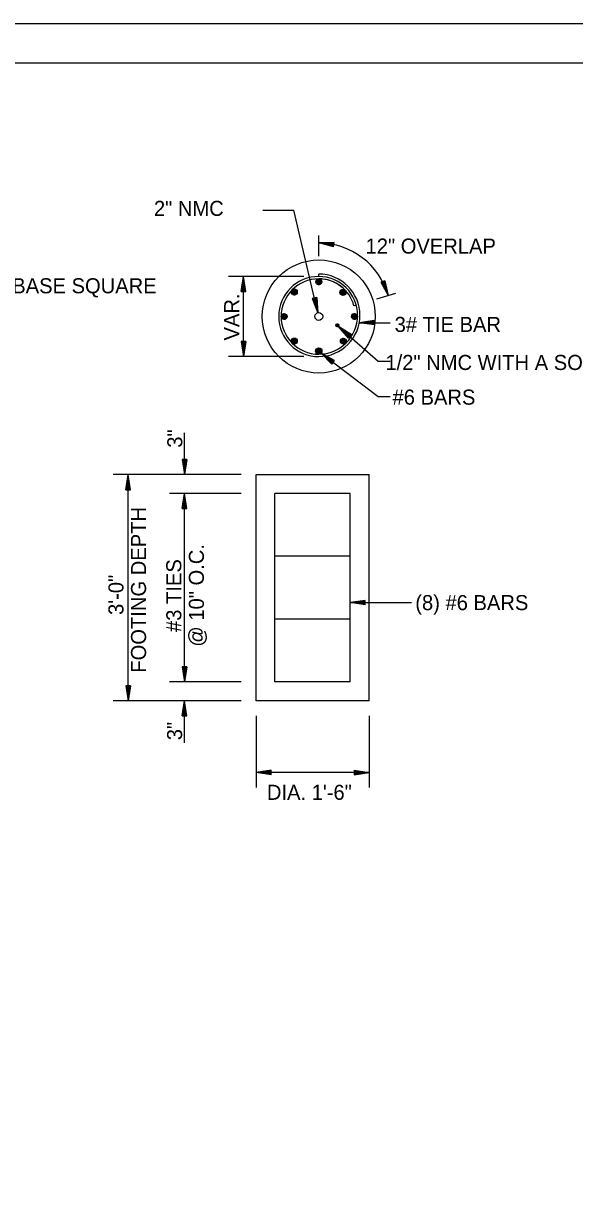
# Model space of a CAD drawing. Extents: x 1370050 to 1370716, y 380076 to 380502.
# Drawn here: x 1370415.9 to 1370525.6, y 380266.8 to 380502.4 of the extents above; entities that cross this region are included whole.
import ezdxf

# ---------------------------------------------------------------- set-up
doc = ezdxf.new("R2010")
doc.units = 0
for name, color, linetype in [('R_Border', 7, 'Continuous'), ('R_Grid', 7, 'Continuous'), ('R_No Plot', 7, 'Continuous')]:
    doc.layers.add(name, color=color, linetype=linetype)

msp = doc.modelspace()

# ---------------------------------------------------------------- linework, layer by layer
at = {"layer": 'R_Border'}
msp.add_line((1370074.49, 380494.58), (1370706.85, 380494.58), dxfattribs=at)
at = {"layer": 'R_Grid'}
for p, q in [((1370463.57, 380465.27), (1370469.71, 380465.27)), ((1370474.52, 380444.85), (1370469.71, 380465.27)), ((1370474.7, 380456.09), (1370474.7, 380460.2)), ((1370477.74, 380458.83), (1370474.71, 380458.76)), ((1370477.62, 380457.93), (1370474.71, 380458.76)), ((1370477.73, 380458.75), (1370475.2, 380458.7)), ((1370477.63, 380458.01), (1370475.2, 380458.7)), ((1370477.72, 380458.68), (1370475.71, 380458.63)), ((1370477.64, 380458.08), (1370475.71, 380458.63)), ((1370477.71, 380458.6), (1370476.21, 380458.57)), ((1370477.65, 380458.16), (1370476.21, 380458.57)), ((1370477.7, 380458.53), (1370476.71, 380458.5)), ((1370477.66, 380458.24), (1370476.71, 380458.5)), ((1370477.62, 380457.93), (1370477.74, 380458.83)), ((1370477.69, 380458.45), (1370477.21, 380458.44)), ((1370477.67, 380458.31), (1370477.21, 380458.44)), ((1370471.7, 380452.06), (1370456.7, 380452.06)), ((1370459.25, 380449.06), (1370459.7, 380452.06)), ((1370459.33, 380449.06), (1370459.7, 380451.56)), ((1370459.7, 380436.12), (1370459.7, 380452.06)), ((1370460.15, 380449.06), (1370459.7, 380452.06)), ((1370460.08, 380449.06), (1370459.7, 380451.56)), ((1370474.1, 380450.96), (1370474.73, 380451.59)), ((1370474.11, 380450.87), (1370474.82, 380451.58)), ((1370474.11, 380451.07), (1370474.62, 380451.58)), ((1370474.14, 380450.79), (1370474.91, 380451.55)), ((1370474.15, 380451.22), (1370474.47, 380451.54)), ((1370474.17, 380450.71), (1370474.98, 380451.52)), ((1370474.21, 380450.65), (1370475.05, 380451.48)), ((1370474.26, 380450.59), (1370475.1, 380451.43)), ((1370474.7, 380452.06), (1370474.7, 380452.53)), ((1370459.25, 380449.06), (1370460.15, 380449.06)), ((1370459.4, 380449.06), (1370459.7, 380451.04)), ((1370459.48, 380449.06), (1370459.7, 380450.54)), ((1370459.56, 380449.06), (1370459.7, 380450.03)), ((1370459.63, 380449.06), (1370459.7, 380449.53)), ((1370460, 380449.06), (1370459.7, 380451.04)), ((1370459.92, 380449.06), (1370459.7, 380450.54)), ((1370459.85, 380449.06), (1370459.7, 380450.03)), ((1370459.77, 380449.06), (1370459.7, 380449.53)), ((1370469.22, 380448.99), (1370469.8, 380449.57)), ((1370469.23, 380448.89), (1370469.9, 380449.56)), ((1370469.24, 380449.12), (1370469.67, 380449.55)), ((1370469.25, 380448.81), (1370469.99, 380449.55)), ((1370469.27, 380448.73), (1370470.06, 380449.52)), ((1370469.31, 380448.66), (1370470.13, 380449.48)), ((1370469.34, 380449.32), (1370469.47, 380449.46)), ((1370469.35, 380448.59), (1370470.2, 380449.44)), ((1370469.4, 380448.54), (1370470.25, 380449.39)), ((1370469.46, 380448.49), (1370470.3, 380449.33)), ((1370469.52, 380448.45), (1370470.34, 380449.27)), ((1370469.6, 380448.41), (1370470.38, 380449.2)), ((1370469.68, 380448.39), (1370470.4, 380449.12)), ((1370474.31, 380450.53), (1370475.16, 380451.38)), ((1370474.37, 380450.49), (1370475.2, 380451.32)), ((1370474.44, 380450.45), (1370475.24, 380451.25)), ((1370474.51, 380450.42), (1370475.27, 380451.18)), ((1370474.6, 380450.4), (1370475.29, 380451.09)), ((1370474.7, 380450.39), (1370475.3, 380451)), ((1370474.81, 380450.4), (1370475.29, 380450.88)), ((1370474.97, 380450.45), (1370475.24, 380450.72)), ((1370478.91, 380448.95), (1370479.46, 380449.5)), ((1370478.92, 380448.85), (1370479.57, 380449.5)), ((1370478.93, 380448.76), (1370479.66, 380449.48)), ((1370478.94, 380449.09), (1370479.33, 380449.47)), ((1370478.96, 380448.68), (1370479.74, 380449.46)), ((1370478.99, 380448.6), (1370479.81, 380449.42)), ((1370479.03, 380448.54), (1370479.87, 380449.38)), ((1370479.08, 380448.48), (1370479.93, 380449.33)), ((1370479.14, 380448.43), (1370479.98, 380449.28)), ((1370479.2, 380448.39), (1370480.02, 380449.21)), ((1370479.27, 380448.35), (1370480.06, 380449.14)), ((1370479.35, 380448.32), (1370480.09, 380449.07)), ((1370487.87, 380451.22), (1370487.03, 380450.9)), ((1370487.03, 380450.9), (1370488.52, 380448.26)), ((1370487.1, 380450.93), (1370488.34, 380448.73)), ((1370487.17, 380450.96), (1370488.16, 380449.21)), ((1370487.24, 380450.98), (1370487.98, 380449.68)), ((1370487.31, 380451.01), (1370487.8, 380450.15)), ((1370487.38, 380451.04), (1370487.62, 380450.62)), ((1370487.52, 380451.09), (1370487.62, 380450.62)), ((1370487.59, 380451.11), (1370487.8, 380450.15)), ((1370487.66, 380451.14), (1370487.98, 380449.68)), ((1370487.73, 380451.17), (1370488.16, 380449.21)), ((1370487.8, 380451.2), (1370488.34, 380448.73)), ((1370487.87, 380451.22), (1370488.52, 380448.26)), ((1370469.77, 380448.37), (1370470.42, 380449.03)), ((1370469.87, 380448.37), (1370470.42, 380448.92)), ((1370470, 380448.4), (1370470.39, 380448.79)), ((1370474.29, 380447.88), (1370473.41, 380447.67)), ((1370473.41, 380447.67), (1370474.52, 380444.85)), ((1370473.49, 380447.69), (1370474.41, 380445.34)), ((1370473.56, 380447.71), (1370474.3, 380445.84)), ((1370473.63, 380447.72), (1370474.18, 380446.33)), ((1370473.71, 380447.74), (1370474.07, 380446.82)), ((1370473.78, 380447.76), (1370473.96, 380447.31)), ((1370473.92, 380447.79), (1370473.96, 380447.31)), ((1370473.99, 380447.81), (1370474.07, 380446.82)), ((1370474.07, 380447.82), (1370474.18, 380446.33)), ((1370474.14, 380447.84), (1370474.3, 380445.84)), ((1370474.22, 380447.86), (1370474.41, 380445.34)), ((1370474.29, 380447.88), (1370474.52, 380444.85)), ((1370479.44, 380448.31), (1370480.11, 380448.98)), ((1370479.54, 380448.3), (1370480.11, 380448.88)), ((1370479.66, 380448.32), (1370480.09, 380448.75)), ((1370479.86, 380448.41), (1370480, 380448.56)), ((1370489.96, 380448.69), (1370486.19, 380447.56)), ((1370467.2, 380444.12), (1370467.77, 380444.69)), ((1370467.21, 380444.02), (1370467.87, 380444.69)), ((1370467.22, 380443.93), (1370467.96, 380444.67)), ((1370467.22, 380444.25), (1370467.65, 380444.67)), ((1370467.25, 380443.85), (1370468.04, 380444.64)), ((1370467.29, 380443.78), (1370468.11, 380444.6)), ((1370467.32, 380444.45), (1370467.44, 380444.57)), ((1370467.33, 380443.72), (1370468.17, 380444.56)), ((1370467.38, 380443.66), (1370468.23, 380444.51)), ((1370467.44, 380443.61), (1370468.28, 380444.45)), ((1370467.5, 380443.57), (1370468.32, 380444.39)), ((1370467.57, 380443.54), (1370468.36, 380444.32)), ((1370481.21, 380444.1), (1370481.8, 380444.69)), ((1370481.21, 380444), (1370481.9, 380444.68)), ((1370481.22, 380444.22), (1370481.68, 380444.68)), ((1370481.23, 380443.91), (1370481.99, 380444.66)), ((1370481.26, 380443.84), (1370482.06, 380444.63)), ((1370481.29, 380444.39), (1370481.51, 380444.61)), ((1370481.3, 380443.77), (1370482.13, 380444.6)), ((1370481.35, 380443.71), (1370482.19, 380444.55)), ((1370481.4, 380443.65), (1370482.25, 380444.5)), ((1370481.46, 380443.6), (1370482.29, 380444.44)), ((1370481.52, 380443.56), (1370482.34, 380444.38)), ((1370482.17, 380446.34), (1370481.72, 380446.21)), ((1370467.65, 380443.51), (1370468.38, 380444.24)), ((1370467.74, 380443.49), (1370468.4, 380444.15)), ((1370467.85, 380443.49), (1370468.4, 380444.04)), ((1370467.98, 380443.52), (1370468.37, 380443.91)), ((1370478.09, 380442.34), (1370478.4, 380442.65)), ((1370478.1, 380442.25), (1370478.49, 380442.64)), ((1370478.12, 380442.48), (1370478.25, 380442.62)), ((1370478.13, 380442.18), (1370478.56, 380442.61)), ((1370478.18, 380442.12), (1370478.62, 380442.56)), ((1370478.24, 380442.07), (1370478.67, 380442.5)), ((1370478.31, 380442.04), (1370478.7, 380442.43)), ((1370478.41, 380442.03), (1370478.71, 380442.33)), ((1370478.56, 380442.07), (1370478.67, 380442.18)), ((1370478.62, 380442.11), (1370486.51, 380435.23)), ((1370480.6, 380439.81), (1370478.62, 380442.11)), ((1370481.18, 380440.49), (1370478.62, 380442.11)), ((1370481.59, 380443.53), (1370482.37, 380444.3)), ((1370481.68, 380443.5), (1370482.39, 380444.22)), ((1370481.77, 380443.49), (1370482.41, 380444.13)), ((1370481.88, 380443.49), (1370482.4, 380444.02)), ((1370482.02, 380443.53), (1370482.37, 380443.88)), ((1370485.77, 380443.31), (1370482.77, 380442.86)), ((1370482.77, 380442.86), (1370488.91, 380442.86)), ((1370485.77, 380442.41), (1370482.77, 380442.86)), ((1370485.77, 380443.23), (1370483.27, 380442.86)), ((1370485.77, 380442.48), (1370483.27, 380442.86)), ((1370485.77, 380443.15), (1370483.79, 380442.86)), ((1370485.77, 380442.56), (1370483.79, 380442.86)), ((1370485.77, 380443.08), (1370484.29, 380442.86)), ((1370485.77, 380442.63), (1370484.29, 380442.86)), ((1370485.77, 380443), (1370484.8, 380442.86)), ((1370485.77, 380442.71), (1370484.8, 380442.86)), ((1370485.77, 380442.93), (1370485.3, 380442.86)), ((1370485.77, 380442.79), (1370485.3, 380442.86)), ((1370485.77, 380442.41), (1370485.77, 380443.31)), ((1370469.22, 380439.16), (1370469.88, 380439.81)), ((1370469.22, 380439.26), (1370469.77, 380439.81)), ((1370469.24, 380439.06), (1370469.97, 380439.79)), ((1370469.25, 380439.39), (1370469.64, 380439.78)), ((1370469.27, 380438.98), (1370470.05, 380439.77)), ((1370469.3, 380438.91), (1370470.12, 380439.73)), ((1370469.34, 380438.85), (1370470.18, 380439.69)), ((1370469.39, 380438.79), (1370470.24, 380439.64)), ((1370480.64, 380439.87), (1370479, 380441.79)), ((1370481.14, 380440.44), (1370479, 380441.79)), ((1370479.01, 380439.11), (1370479.68, 380439.78)), ((1370479.01, 380439.21), (1370479.58, 380439.78)), ((1370479.03, 380439.02), (1370479.77, 380439.76)), ((1370479.03, 380439.34), (1370479.46, 380439.76)), ((1370479.06, 380438.94), (1370479.85, 380439.73)), ((1370479.1, 380438.87), (1370479.92, 380439.7)), ((1370479.13, 380439.54), (1370479.25, 380439.66)), ((1370479.14, 380438.81), (1370479.98, 380439.65)), ((1370481.09, 380440.38), (1370479.39, 380441.45)), ((1370480.69, 380439.93), (1370479.39, 380441.45)), ((1370480.74, 380439.98), (1370479.77, 380441.12)), ((1370481.04, 380440.32), (1370479.77, 380441.12)), ((1370480.99, 380440.26), (1370480.15, 380440.79)), ((1370480.79, 380440.04), (1370480.15, 380440.79)), ((1370480.94, 380440.21), (1370480.53, 380440.46)), ((1370480.84, 380440.1), (1370480.53, 380440.46)), ((1370480.6, 380439.81), (1370481.18, 380440.49)), ((1370459.25, 380439.12), (1370459.7, 380436.12)), ((1370460.15, 380439.12), (1370459.25, 380439.12)), ((1370459.33, 380439.12), (1370459.7, 380436.62)), ((1370459.4, 380439.12), (1370459.7, 380437.14)), ((1370459.48, 380439.12), (1370459.7, 380437.64)), ((1370459.55, 380439.12), (1370459.7, 380438.15)), ((1370459.63, 380439.12), (1370459.7, 380438.65)), ((1370460.15, 380439.12), (1370459.7, 380436.12)), ((1370459.85, 380439.12), (1370459.7, 380438.15)), ((1370460, 380439.12), (1370459.7, 380437.14)), ((1370460.08, 380439.12), (1370459.7, 380436.62)), ((1370459.92, 380439.12), (1370459.7, 380437.64)), ((1370459.77, 380439.12), (1370459.7, 380438.65)), ((1370469.45, 380438.74), (1370470.29, 380439.59)), ((1370469.51, 380438.7), (1370470.33, 380439.52)), ((1370469.58, 380438.66), (1370470.37, 380439.45)), ((1370469.66, 380438.63), (1370470.4, 380439.38)), ((1370469.75, 380438.62), (1370470.42, 380439.29)), ((1370469.85, 380438.61), (1370470.42, 380439.19)), ((1370469.97, 380438.63), (1370470.4, 380439.06)), ((1370470.17, 380438.72), (1370470.31, 380438.86)), ((1370474.08, 380437.16), (1370474.76, 380437.84)), ((1370474.08, 380437.26), (1370474.65, 380437.84)), ((1370474.09, 380437.07), (1370474.85, 380437.82)), ((1370474.1, 380437.39), (1370474.52, 380437.81)), ((1370474.12, 380436.99), (1370474.93, 380437.8)), ((1370474.15, 380436.91), (1370475, 380437.76)), ((1370474.19, 380436.85), (1370475.07, 380437.72)), ((1370474.24, 380437.64), (1370474.28, 380437.68)), ((1370474.24, 380436.79), (1370475.13, 380437.67)), ((1370474.3, 380436.74), (1370475.18, 380437.62)), ((1370474.36, 380436.69), (1370475.22, 380437.56)), ((1370474.42, 380436.65), (1370475.26, 380437.49)), ((1370474.5, 380436.62), (1370475.29, 380437.42)), ((1370474.58, 380436.6), (1370475.32, 380437.33)), ((1370479.19, 380438.75), (1370480.04, 380439.6)), ((1370479.25, 380438.7), (1370480.09, 380439.54)), ((1370479.31, 380438.66), (1370480.13, 380439.48)), ((1370479.38, 380438.63), (1370480.16, 380439.41)), ((1370479.46, 380438.6), (1370480.19, 380439.33)), ((1370479.55, 380438.58), (1370480.21, 380439.24)), ((1370479.66, 380438.58), (1370480.21, 380439.13)), ((1370479.79, 380438.61), (1370480.18, 380439)), ((1370471.7, 380436.12), (1370456.7, 380436.12)), ((1370474.68, 380436.59), (1370475.33, 380437.24)), ((1370474.79, 380436.6), (1370475.32, 380437.13)), ((1370474.94, 380436.64), (1370475.28, 380436.98)), ((1370475.15, 380436.78), (1370486.51, 380428.19)), ((1370477.28, 380434.61), (1370475.15, 380436.78)), ((1370477.82, 380435.33), (1370475.15, 380436.78)), ((1370477.32, 380434.67), (1370475.55, 380436.48)), ((1370477.77, 380435.27), (1370475.55, 380436.48)), ((1370477.73, 380435.21), (1370475.96, 380436.17)), ((1370477.37, 380434.73), (1370475.96, 380436.17)), ((1370477.41, 380434.79), (1370476.36, 380435.86)), ((1370477.68, 380435.15), (1370476.36, 380435.86)), ((1370477.63, 380435.09), (1370476.77, 380435.56)), ((1370477.46, 380434.86), (1370476.77, 380435.56)), ((1370477.59, 380435.03), (1370477.17, 380435.26)), ((1370477.5, 380434.92), (1370477.17, 380435.26)), ((1370477.28, 380434.61), (1370477.82, 380435.33)), ((1370486.51, 380435.23), (1370488.91, 380435.23)), ((1370486.51, 380428.19), (1370488.91, 380428.19)), ((1370447.97, 380412.62), (1370447.97, 380420.96)), ((1370447.52, 380415.62), (1370447.97, 380412.62)), ((1370448.42, 380415.62), (1370447.52, 380415.62)), ((1370447.59, 380415.62), (1370447.97, 380413.12)), ((1370447.67, 380415.62), (1370447.97, 380413.64)), ((1370447.74, 380415.62), (1370447.97, 380414.14)), ((1370447.82, 380415.62), (1370447.97, 380414.65)), ((1370447.9, 380415.62), (1370447.97, 380415.15)), ((1370448.42, 380415.62), (1370447.97, 380412.62)), ((1370448.11, 380415.62), (1370447.97, 380414.65)), ((1370448.27, 380415.62), (1370447.97, 380413.64)), ((1370448.34, 380415.62), (1370447.97, 380413.12)), ((1370448.19, 380415.62), (1370447.97, 380414.14)), ((1370448.04, 380415.62), (1370447.97, 380415.15)), ((1370459.22, 380412.62), (1370433.72, 380412.62)), ((1370436.27, 380409.62), (1370436.72, 380412.62)), ((1370436.34, 380409.62), (1370436.72, 380412.12)), ((1370436.42, 380409.62), (1370436.72, 380411.61)), ((1370436.72, 380367.62), (1370436.72, 380412.62)), ((1370437.17, 380409.62), (1370436.72, 380412.62)), ((1370437.09, 380409.62), (1370436.72, 380412.12)), ((1370437.02, 380409.62), (1370436.72, 380411.61)), ((1370462.22, 380367.62), (1370462.22, 380412.62)), ((1370462.22, 380412.62), (1370484.72, 380412.62)), ((1370484.72, 380367.62), (1370484.72, 380412.62)), ((1370436.27, 380409.62), (1370437.17, 380409.62)), ((1370436.49, 380409.62), (1370436.72, 380411.11)), ((1370436.57, 380409.62), (1370436.72, 380410.6)), ((1370436.65, 380409.62), (1370436.72, 380410.1)), ((1370436.94, 380409.62), (1370436.72, 380411.11)), ((1370436.86, 380409.62), (1370436.72, 380410.6)), ((1370436.79, 380409.62), (1370436.72, 380410.1)), ((1370459.22, 380408.87), (1370444.97, 380408.87)), ((1370447.52, 380405.87), (1370447.97, 380408.87)), ((1370447.59, 380405.87), (1370447.97, 380408.37)), ((1370447.67, 380405.87), (1370447.97, 380407.86)), ((1370447.74, 380405.87), (1370447.97, 380407.36)), ((1370447.82, 380405.87), (1370447.97, 380406.85)), ((1370447.97, 380371.37), (1370447.97, 380408.87)), ((1370448.42, 380405.87), (1370447.97, 380408.87)), ((1370448.34, 380405.87), (1370447.97, 380408.37)), ((1370448.27, 380405.87), (1370447.97, 380407.86)), ((1370448.19, 380405.87), (1370447.97, 380407.36)), ((1370448.11, 380405.87), (1370447.97, 380406.85)), ((1370480.97, 380408.87), (1370465.97, 380408.87)), ((1370465.97, 380371.37), (1370465.97, 380408.87)), ((1370480.97, 380371.37), (1370480.97, 380408.87)), ((1370447.52, 380405.87), (1370448.42, 380405.87)), ((1370447.9, 380405.87), (1370447.97, 380406.35)), ((1370448.04, 380405.87), (1370447.97, 380406.35)), ((1370480.97, 380396.37), (1370465.97, 380396.37)), ((1370483.97, 380387.61), (1370480.97, 380387.16)), ((1370483.97, 380386.71), (1370480.97, 380387.16)), ((1370480.97, 380387.16), (1370493.19, 380387.16)), ((1370483.97, 380387.54), (1370481.47, 380387.16)), ((1370483.97, 380386.79), (1370481.47, 380387.16)), ((1370483.97, 380387.46), (1370481.99, 380387.16)), ((1370483.97, 380386.86), (1370481.99, 380387.16)), ((1370483.97, 380387.39), (1370482.49, 380387.16)), ((1370483.97, 380386.94), (1370482.49, 380387.16)), ((1370483.97, 380387.31), (1370483, 380387.16)), ((1370483.97, 380387.02), (1370483, 380387.16)), ((1370483.97, 380387.23), (1370483.5, 380387.16)), ((1370483.97, 380387.09), (1370483.5, 380387.16)), ((1370483.97, 380386.71), (1370483.97, 380387.61)), ((1370480.97, 380383.87), (1370465.97, 380383.87)), ((1370447.52, 380374.37), (1370447.97, 380371.37)), ((1370448.42, 380374.37), (1370447.52, 380374.37)), ((1370447.59, 380374.37), (1370447.97, 380371.87)), ((1370447.67, 380374.37), (1370447.97, 380372.39)), ((1370447.74, 380374.37), (1370447.97, 380372.89)), ((1370447.82, 380374.37), (1370447.97, 380373.4)), ((1370447.9, 380374.37), (1370447.97, 380373.9)), ((1370448.42, 380374.37), (1370447.97, 380371.37)), ((1370448.11, 380374.37), (1370447.97, 380373.4)), ((1370448.27, 380374.37), (1370447.97, 380372.39)), ((1370448.34, 380374.37), (1370447.97, 380371.87)), ((1370448.19, 380374.37), (1370447.97, 380372.89)), ((1370448.04, 380374.37), (1370447.97, 380373.9)), ((1370459.22, 380371.37), (1370444.97, 380371.37)), ((1370480.97, 380371.37), (1370465.97, 380371.37)), ((1370436.27, 380370.62), (1370436.72, 380367.62)), ((1370437.17, 380370.62), (1370436.27, 380370.62)), ((1370436.34, 380370.62), (1370436.72, 380368.12)), ((1370436.42, 380370.62), (1370436.72, 380368.64)), ((1370436.49, 380370.62), (1370436.72, 380369.14)), ((1370436.57, 380370.62), (1370436.72, 380369.65)), ((1370436.65, 380370.62), (1370436.72, 380370.15)), ((1370437.17, 380370.62), (1370436.72, 380367.62)), ((1370436.86, 380370.62), (1370436.72, 380369.65)), ((1370437.02, 380370.62), (1370436.72, 380368.64)), ((1370437.09, 380370.62), (1370436.72, 380368.12)), ((1370436.94, 380370.62), (1370436.72, 380369.14)), ((1370436.79, 380370.62), (1370436.72, 380370.15)), ((1370459.22, 380367.62), (1370433.72, 380367.62)), ((1370447.52, 380364.62), (1370447.97, 380367.62)), ((1370447.59, 380364.62), (1370447.97, 380367.12)), ((1370447.67, 380364.62), (1370447.97, 380366.61)), ((1370447.97, 380359.28), (1370447.97, 380367.62)), ((1370448.42, 380364.62), (1370447.97, 380367.62)), ((1370448.34, 380364.62), (1370447.97, 380367.12)), ((1370448.27, 380364.62), (1370447.97, 380366.61)), ((1370484.72, 380367.62), (1370462.22, 380367.62)), ((1370447.52, 380364.62), (1370448.42, 380364.62)), ((1370447.74, 380364.62), (1370447.97, 380366.11)), ((1370447.82, 380364.62), (1370447.97, 380365.6)), ((1370447.9, 380364.62), (1370447.97, 380365.1)), ((1370448.19, 380364.62), (1370447.97, 380366.11)), ((1370448.11, 380364.62), (1370447.97, 380365.6)), ((1370448.04, 380364.62), (1370447.97, 380365.1)), ((1370462.22, 380364.62), (1370462.22, 380350.37)), ((1370484.72, 380364.62), (1370484.72, 380350.37)), ((1370465.22, 380353.82), (1370462.22, 380353.37)), ((1370484.72, 380353.37), (1370462.22, 380353.37)), ((1370465.22, 380352.92), (1370462.22, 380353.37)), ((1370465.22, 380353.75), (1370462.72, 380353.37)), ((1370465.22, 380353), (1370462.72, 380353.37)), ((1370465.22, 380353.67), (1370463.23, 380353.37)), ((1370465.22, 380353.07), (1370463.23, 380353.37)), ((1370465.22, 380353.6), (1370463.73, 380353.37)), ((1370465.22, 380353.15), (1370463.73, 380353.37)), ((1370465.22, 380353.52), (1370464.24, 380353.37)), ((1370465.22, 380353.23), (1370464.24, 380353.37)), ((1370465.22, 380353.44), (1370464.74, 380353.37)), ((1370465.22, 380353.3), (1370464.74, 380353.37)), ((1370465.22, 380352.92), (1370465.22, 380353.82)), ((1370481.72, 380353.82), (1370484.72, 380353.37)), ((1370481.72, 380353.82), (1370481.72, 380352.92)), ((1370481.72, 380353.75), (1370484.22, 380353.37)), ((1370481.72, 380353.67), (1370483.7, 380353.37)), ((1370481.72, 380353.6), (1370483.2, 380353.37)), ((1370481.72, 380353.52), (1370482.69, 380353.37)), ((1370481.72, 380353.44), (1370482.19, 380353.37)), ((1370481.72, 380352.92), (1370484.72, 380353.37)), ((1370481.72, 380353.23), (1370482.69, 380353.37)), ((1370481.72, 380353.07), (1370483.7, 380353.37)), ((1370481.72, 380353), (1370484.22, 380353.37)), ((1370481.72, 380353.15), (1370483.2, 380353.37)), ((1370481.72, 380353.3), (1370482.19, 380353.37))]:
    msp.add_line(p, q, dxfattribs=at)
for centre, radius in [((1370474.7, 380444.09), 11.25), ((1370474.7, 380450.99), 0.6), ((1370469.82, 380448.97), 0.6), ((1370479.51, 380448.9), 0.6), ((1370467.8, 380444.09), 0.6), ((1370474.7, 380444.09), 0.781), ((1370481.81, 380444.09), 0.6), ((1370478.4, 380442.34), 0.312), ((1370469.82, 380439.21), 0.6), ((1370479.61, 380439.18), 0.6), ((1370474.7, 380437.22), 0.625)]:
    msp.add_circle(centre, radius, dxfattribs=at)
for centre, radius, start, end in [((1370474.7, 380444.33), 14.37, 15.8939, 90), ((1370474.7, 380444.09), 7.97, 90, 270), ((1370474.7, 380444.09), 7.5, 90, 270), ((1370474.7, 380444.33), 8.2, 270, 90), ((1370474.7, 380444.33), 7.73, 270, 90), ((1370474.7, 380444.33), 7.26, 43.6894, 90), ((1370474.7, 380444.33), 7.26, 15.0162, 90)]:
    msp.add_arc(centre, radius, start, end, dxfattribs=at)
at = {"layer": 'R_No Plot'}
msp.add_line((1370049.68, 380502.37), (1370716.35, 380502.37), dxfattribs=at)
msp.add_lwpolyline([(1370049.67, 380502.37), (1370716.35, 380502.37), (1370716.35, 380075.69), (1370049.67, 380075.69)], close=True, dxfattribs=at)

# ---------------------------------------------------------------- texts
at = {"layer": 'R_Grid'}
for s, p in [('2" NMC', (1370441.87, 380464.11)), ('12" OVERLAP', (1370484.02, 380456.61)), ('ANCHOR BASE SQUARE', (1370395.15, 380448.71)), ('3# TIE BAR', (1370489.81, 380441.02)), (' 1/2" NMC WITH A SOLID 1C/#8 A.W.G., E.G.C.', (1370486.86, 380433.45)), ('#6 BARS', (1370489.39, 380426.55)), ('(8) #6 BARS', (1370493.92, 380385.66)), ('DIA. 1\'-6"', (1370464.37, 380347.91))]:
    msp.add_text(s, height=3, dxfattribs=at).set_placement(p)
for s, p in [('VAR.', (1370458.85, 380439.32)), ('3"', (1370447.52, 380417.98)), ('FOOTING DEPTH', (1370440.3, 380373.21)), ('@ 10" O.C.', (1370451.82, 380378.38)), ('#3 TIES', (1370447.32, 380381.31)), ('3\'-0"', (1370435.8, 380384.7)), ('3"', (1370447.48, 380359.77))]:
    msp.add_text(s, height=3, rotation=90, dxfattribs=at).set_placement(p)

doc.saveas('drawing.dxf')
